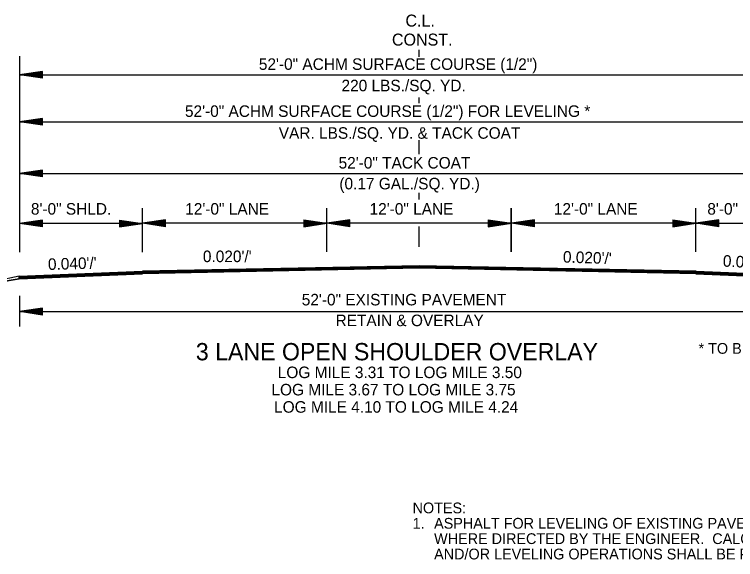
# Model space of a CAD drawing. Extents: x 542112 to 1930787, y -1968972 to 596640.
# Drawn here: x 546718.3 to 547187.5, y -1946518.3 to -1946163.6 of the extents above; entities that cross this region are included whole.
import ezdxf

# ---------------------------------------------------------------- set-up
doc = ezdxf.new("R2010")
doc.units = 0
for name, color, linetype in [('R_Border Notes', 7, 'Continuous'), ('R_Border Prem', 7, 'Continuous'), ('R_Draft', 7, 'Continuous')]:
    doc.layers.add(name, color=color, linetype=linetype)

msp = doc.modelspace()

# ---------------------------------------------------------------- linework, layer by layer
at = {"layer": 'R_Draft'}
for p, q in [((546721.58, -1946190.89), (546721.58, -1946318.31)), ((546981.62, -1946191.17), (546981.62, -1946186.75)), ((546736.66, -1946200.68), (546721.66, -1946202.93)), ((546736.66, -1946205.18), (546736.66, -1946200.68)), ((546721.66, -1946202.93), (547241.62, -1946202.93)), ((546736.66, -1946205.18), (546721.66, -1946202.93)), ((546736.66, -1946201.05), (546724.17, -1946202.93)), ((546736.66, -1946204.8), (546724.17, -1946202.93)), ((546736.66, -1946201.44), (546726.75, -1946202.93)), ((546736.66, -1946204.42), (546726.75, -1946202.93)), ((546736.66, -1946201.81), (546729.25, -1946202.93)), ((546736.66, -1946204.05), (546729.25, -1946202.93)), ((546736.66, -1946202.19), (546731.79, -1946202.93)), ((546736.66, -1946203.66), (546731.79, -1946202.93)), ((546736.66, -1946202.58), (546734.29, -1946202.93)), ((546736.66, -1946203.28), (546734.29, -1946202.93)), ((546981.62, -1946221.3), (546981.62, -1946217.62)), ((546736.62, -1946231.28), (546721.62, -1946233.53)), ((546721.62, -1946233.53), (547241.62, -1946233.53)), ((546736.62, -1946235.78), (546721.62, -1946233.53)), ((546736.62, -1946231.65), (546724.12, -1946233.53)), ((546736.62, -1946235.4), (546724.12, -1946233.53)), ((546736.62, -1946232.03), (546726.7, -1946233.53)), ((546736.62, -1946235.02), (546726.7, -1946233.53)), ((546736.62, -1946232.41), (546729.2, -1946233.53)), ((546736.62, -1946234.64), (546729.2, -1946233.53)), ((546736.62, -1946232.79), (546731.74, -1946233.53)), ((546736.62, -1946234.25), (546731.74, -1946233.53)), ((546736.62, -1946233.17), (546734.25, -1946233.53)), ((546736.62, -1946233.88), (546734.25, -1946233.53)), ((546736.62, -1946235.78), (546736.62, -1946231.28)), ((546981.62, -1946254.65), (546981.62, -1946245.35)), ((546736.62, -1946264.87), (546721.62, -1946267.12)), ((546736.62, -1946265.25), (546724.12, -1946267.12)), ((546736.62, -1946265.63), (546726.7, -1946267.12)), ((546736.62, -1946266.01), (546729.2, -1946267.12)), ((546736.62, -1946266.39), (546731.74, -1946267.12)), ((546736.62, -1946269.37), (546736.62, -1946264.87)), ((546721.62, -1946267.12), (547241.62, -1946267.12)), ((546736.62, -1946269.37), (546721.62, -1946267.12)), ((546736.62, -1946269), (546724.12, -1946267.12)), ((546736.62, -1946268.62), (546726.7, -1946267.12)), ((546736.62, -1946268.24), (546729.2, -1946267.12)), ((546736.62, -1946267.85), (546731.74, -1946267.12)), ((546736.62, -1946266.77), (546734.25, -1946267.12)), ((546736.62, -1946267.48), (546734.25, -1946267.12)), ((546981.62, -1946284.09), (546981.62, -1946279.72)), ((546801.62, -1946318.14), (546801.62, -1946289.59)), ((546801.62, -1946318.31), (546801.62, -1946289.59)), ((546921.62, -1946318.14), (546921.62, -1946289.59)), ((547041.54, -1946299.48), (547041.54, -1946289.59)), ((547041.62, -1946318.14), (547041.62, -1946289.59)), ((547161.62, -1946318.14), (547161.62, -1946289.59)), ((546736.62, -1946297.4), (546721.62, -1946299.65)), ((546736.62, -1946297.78), (546724.12, -1946299.65)), ((546736.62, -1946298.16), (546726.7, -1946299.65)), ((546736.62, -1946298.54), (546729.2, -1946299.65)), ((546736.62, -1946298.92), (546731.74, -1946299.65)), ((546736.62, -1946301.9), (546736.62, -1946297.4)), ((546786.62, -1946297.4), (546801.62, -1946299.65)), ((546786.62, -1946297.4), (546786.62, -1946301.9)), ((546786.62, -1946297.78), (546799.11, -1946299.65)), ((546786.62, -1946298.16), (546796.53, -1946299.65)), ((546786.62, -1946298.54), (546794.03, -1946299.65)), ((546786.62, -1946298.93), (546791.49, -1946299.65)), ((546816.62, -1946297.23), (546801.62, -1946299.48)), ((546816.62, -1946297.61), (546804.12, -1946299.48)), ((546816.62, -1946297.99), (546806.7, -1946299.48)), ((546816.62, -1946298.37), (546809.2, -1946299.48)), ((546816.62, -1946298.75), (546811.74, -1946299.48)), ((546816.62, -1946299.13), (546814.25, -1946299.48)), ((546816.62, -1946301.73), (546816.62, -1946297.23)), ((546906.62, -1946297.23), (546921.62, -1946299.48)), ((546906.62, -1946297.23), (546906.62, -1946301.73)), ((546906.62, -1946297.61), (546919.11, -1946299.48)), ((546906.62, -1946297.99), (546916.53, -1946299.48)), ((546906.62, -1946298.37), (546914.03, -1946299.48)), ((546906.62, -1946298.76), (546911.49, -1946299.48)), ((546906.62, -1946299.13), (546908.99, -1946299.48)), ((546936.62, -1946297.23), (546921.62, -1946299.48)), ((546936.62, -1946297.61), (546924.12, -1946299.48)), ((546936.62, -1946297.99), (546926.7, -1946299.48)), ((546936.62, -1946298.37), (546929.2, -1946299.48)), ((546936.62, -1946298.75), (546931.74, -1946299.48)), ((546936.62, -1946299.13), (546934.25, -1946299.48)), ((546936.62, -1946301.73), (546936.62, -1946297.23)), ((547026.62, -1946297.23), (547041.62, -1946299.48)), ((547026.62, -1946297.23), (547026.62, -1946301.73)), ((547026.62, -1946297.61), (547039.11, -1946299.48)), ((547026.62, -1946297.99), (547036.53, -1946299.48)), ((547026.62, -1946298.37), (547034.03, -1946299.48)), ((547026.62, -1946298.76), (547031.49, -1946299.48)), ((547026.62, -1946299.13), (547028.99, -1946299.48)), ((547056.62, -1946297.23), (547041.62, -1946299.48)), ((547056.62, -1946297.61), (547044.12, -1946299.48)), ((547056.62, -1946297.99), (547046.7, -1946299.48)), ((547056.62, -1946298.37), (547049.2, -1946299.48)), ((547056.62, -1946298.75), (547051.74, -1946299.48)), ((547056.62, -1946299.13), (547054.25, -1946299.48)), ((547056.62, -1946301.73), (547056.62, -1946297.23)), ((547146.62, -1946297.23), (547161.62, -1946299.48)), ((547146.62, -1946297.23), (547146.62, -1946301.73)), ((547146.62, -1946297.61), (547159.11, -1946299.48)), ((547146.62, -1946297.99), (547156.53, -1946299.48)), ((547146.62, -1946298.37), (547154.03, -1946299.48)), ((547146.62, -1946298.76), (547151.49, -1946299.48)), ((547146.62, -1946299.13), (547148.99, -1946299.48)), ((547176.62, -1946297.23), (547161.62, -1946299.48)), ((547176.62, -1946297.61), (547164.12, -1946299.48)), ((547176.62, -1946297.99), (547166.7, -1946299.48)), ((547176.62, -1946298.37), (547169.2, -1946299.48)), ((547176.62, -1946298.75), (547171.74, -1946299.48)), ((547176.62, -1946299.13), (547174.25, -1946299.48)), ((547176.62, -1946301.73), (547176.62, -1946297.23)), ((546801.62, -1946299.65), (546721.62, -1946299.65)), ((546736.62, -1946301.9), (546721.62, -1946299.65)), ((546736.62, -1946301.53), (546724.12, -1946299.65)), ((546736.62, -1946301.15), (546726.7, -1946299.65)), ((546736.62, -1946300.77), (546729.2, -1946299.65)), ((546736.62, -1946300.38), (546731.74, -1946299.65)), ((546736.62, -1946299.3), (546734.25, -1946299.65)), ((546736.62, -1946300.01), (546734.25, -1946299.65)), ((546786.62, -1946299.3), (546788.99, -1946299.65)), ((546786.62, -1946301.9), (546801.62, -1946299.65)), ((546786.62, -1946300.39), (546791.49, -1946299.65)), ((546786.62, -1946301.15), (546796.53, -1946299.65)), ((546786.62, -1946301.53), (546799.11, -1946299.65)), ((546786.62, -1946300.77), (546794.03, -1946299.65)), ((546786.62, -1946300.01), (546788.99, -1946299.65)), ((546921.62, -1946299.48), (546801.62, -1946299.48)), ((546816.62, -1946301.73), (546801.62, -1946299.48)), ((546816.62, -1946301.36), (546804.12, -1946299.48)), ((546816.62, -1946300.98), (546806.7, -1946299.48)), ((546816.62, -1946300.6), (546809.2, -1946299.48)), ((546816.62, -1946300.21), (546811.74, -1946299.48)), ((546816.62, -1946299.84), (546814.25, -1946299.48)), ((546906.62, -1946301.73), (546921.62, -1946299.48)), ((546906.62, -1946300.22), (546911.49, -1946299.48)), ((546906.62, -1946300.98), (546916.53, -1946299.48)), ((546906.62, -1946301.36), (546919.11, -1946299.48)), ((546906.62, -1946300.6), (546914.03, -1946299.48)), ((546906.62, -1946299.84), (546908.99, -1946299.48)), ((547041.62, -1946299.48), (546921.62, -1946299.48)), ((546936.62, -1946301.73), (546921.62, -1946299.48)), ((546936.62, -1946301.36), (546924.12, -1946299.48)), ((546936.62, -1946300.98), (546926.7, -1946299.48)), ((546936.62, -1946300.6), (546929.2, -1946299.48)), ((546936.62, -1946300.21), (546931.74, -1946299.48)), ((546936.62, -1946299.84), (546934.25, -1946299.48)), ((546981.62, -1946314.89), (546981.62, -1946301.6)), ((547026.62, -1946301.73), (547041.62, -1946299.48)), ((547026.62, -1946300.22), (547031.49, -1946299.48)), ((547026.62, -1946300.98), (547036.53, -1946299.48)), ((547026.62, -1946301.36), (547039.11, -1946299.48)), ((547026.62, -1946300.6), (547034.03, -1946299.48)), ((547026.62, -1946299.84), (547028.99, -1946299.48)), ((547041.54, -1946318.14), (547041.54, -1946299.48)), ((547161.62, -1946299.48), (547041.62, -1946299.48)), ((547056.62, -1946301.73), (547041.62, -1946299.48)), ((547056.62, -1946301.36), (547044.12, -1946299.48)), ((547056.62, -1946300.98), (547046.7, -1946299.48)), ((547056.62, -1946300.6), (547049.2, -1946299.48)), ((547056.62, -1946300.21), (547051.74, -1946299.48)), ((547056.62, -1946299.84), (547054.25, -1946299.48)), ((547146.62, -1946301.73), (547161.62, -1946299.48)), ((547146.62, -1946300.22), (547151.49, -1946299.48)), ((547146.62, -1946300.98), (547156.53, -1946299.48)), ((547146.62, -1946301.36), (547159.11, -1946299.48)), ((547146.62, -1946300.6), (547154.03, -1946299.48)), ((547146.62, -1946299.84), (547148.99, -1946299.48)), ((547161.62, -1946299.48), (547241.62, -1946299.48)), ((547176.62, -1946301.73), (547161.62, -1946299.48)), ((547176.62, -1946301.36), (547164.12, -1946299.48)), ((547176.62, -1946300.98), (547166.7, -1946299.48)), ((547176.62, -1946300.6), (547169.2, -1946299.48)), ((547176.62, -1946300.21), (547171.74, -1946299.48)), ((547176.62, -1946299.84), (547174.25, -1946299.48)), ((546981.62, -1946327.09), (546801.62, -1946330.69)), ((546981.62, -1946327.39), (546801.62, -1946330.99)), ((547161.8, -1946330.99), (546981.61, -1946327.39)), ((547161.8, -1946330.69), (546981.62, -1946327.09)), ((546721.36, -1946333.9), (546801.62, -1946330.69)), ((546721.36, -1946334.2), (546801.63, -1946330.99)), ((546721.36, -1946334.5), (546801.64, -1946331.29)), ((546721.36, -1946334.8), (546801.65, -1946331.59)), ((546721.36, -1946335.1), (546801.66, -1946331.89)), ((546981.63, -1946327.69), (546801.63, -1946331.29)), ((546981.63, -1946327.99), (546801.63, -1946331.59)), ((546981.64, -1946328.29), (546801.64, -1946331.89)), ((546981.65, -1946328.59), (546801.65, -1946332.19)), ((546981.65, -1946328.79), (546801.65, -1946332.39)), ((547161.77, -1946332.39), (546981.58, -1946328.79)), ((547161.78, -1946331.89), (546981.59, -1946328.29)), ((547161.77, -1946332.19), (546981.59, -1946328.59)), ((547161.79, -1946331.29), (546981.6, -1946327.69)), ((547161.79, -1946331.59), (546981.6, -1946327.99)), ((547161.76, -1946331.89), (547242.07, -1946335.11)), ((547161.77, -1946331.59), (547242.07, -1946334.8)), ((547161.78, -1946331.29), (547242.07, -1946334.5)), ((547161.79, -1946330.99), (547242.07, -1946334.2)), ((547161.8, -1946330.69), (547242.07, -1946333.9)), ((546721.36, -1946335.6), (546621.29, -1946352.28)), ((546721.36, -1946333.9), (546683.86, -1946341.84)), ((546683.86, -1946341.84), (546721.36, -1946335.6)), ((546721.36, -1946335.4), (546801.68, -1946332.19)), ((546721.36, -1946335.6), (546801.68, -1946332.39)), ((546721.36, -1946335.6), (546721.36, -1946333.9)), ((546721.36, -1946333.9), (546721.36, -1946335.6)), ((546721.36, -1946335.6), (546721.36, -1946335.6)), ((547161.74, -1946332.19), (547242.07, -1946335.41)), ((547161.74, -1946332.39), (547242.08, -1946335.61)), ((546721.62, -1946346.7), (546721.62, -1946366.7)), ((546736.62, -1946354.7), (546721.62, -1946356.95)), ((546736.62, -1946355.07), (546724.12, -1946356.95)), ((546736.62, -1946355.46), (546726.7, -1946356.95)), ((546736.62, -1946359.2), (546736.62, -1946354.7)), ((546721.62, -1946356.95), (547241.62, -1946356.95)), ((546736.62, -1946359.2), (546721.62, -1946356.95)), ((546736.62, -1946358.82), (546724.12, -1946356.95)), ((546736.62, -1946358.44), (546726.7, -1946356.95)), ((546736.62, -1946355.83), (546729.2, -1946356.95)), ((546736.62, -1946358.07), (546729.2, -1946356.95)), ((546736.62, -1946356.21), (546731.74, -1946356.95)), ((546736.62, -1946357.68), (546731.74, -1946356.95)), ((546736.62, -1946356.6), (546734.25, -1946356.95)), ((546736.62, -1946357.3), (546734.25, -1946356.95))]:
    msp.add_line(p, q, dxfattribs=at)

# ---------------------------------------------------------------- texts
at = {"layer": 'R_Border Notes'}
for s, p in [('NOTES: ', (546977.36, -1946488.18)), ('1.', (546977.36, -1946498.18)), ('ASPHALT FOR LEVELING OF EXISTING PAVEMENT SHALL BE PLACED ONLY IF AND', (546991.36, -1946498.18)), ('WHERE DIRECTED BY THE ENGINEER.  CALCULATIONS FOR THE AMOUNT OF LEVELING', (546991.36, -1946508.18)), ('AND/OR LEVELING OPERATIONS SHALL BE PERFORMED BEFORE CONSTRUCTING NOTCH', (546991.36, -1946518.18))]:
    msp.add_text(s, height=7, dxfattribs=at).set_placement(p)
at = {"layer": 'R_Border Prem'}
msp.add_text('* TO BE USED IF AND WHERE DIRECTED BY THE ENGINEER.', height=7, dxfattribs=at).set_placement((547163.42, -1946384.41))
at = {"layer": 'R_Draft'}
for s, height, p in [('C.L.', 7.8, (546972.72, -1946171.55)), ('CONST.', 7.8, (546963.94, -1946183.92)), ('52\'-0" ACHM SURFACE COURSE (1/2")', 7.5, (546877.33, -1946199.71)), ('220 LBS./SQ. YD. ', 7.5, (546931.12, -1946213.65)), ('52\'-0" ACHM SURFACE COURSE (1/2") FOR LEVELING *', 7.5, (546829.26, -1946230.3)), ('VAR. LBS./SQ. YD. & TACK COAT', 7.5, (546890.3, -1946244.52)), ('52\'-0" TACK COAT', 7.5, (546929.22, -1946263.9)), ('(0.17 GAL./SQ. YD.)', 7.5, (546929.72, -1946277.45)), ('8\'-0" SHLD.', 7.5, (546729.01, -1946293.88)), ('12\'-0" LANE', 7.5, (546829.43, -1946293.88)), ('12\'-0" LANE', 7.5, (546949.39, -1946293.88)), ('12\'-0" LANE', 7.5, (547069.3, -1946293.88)), ('8\'-0" SHLD.', 7.5, (547169.14, -1946293.88)), ("0.020'/'", 7.5, (546840.92, -1946324.77)), ('52\'-0" EXISTING PAVEMENT', 7.5, (546905.25, -1946352.93)), ('RETAIN & OVERLAY', 7.5, (546927.25, -1946366.44)), ('3 LANE OPEN SHOULDER OVERLAY', 11.25, (546836.34, -1946388.66)), ('LOG MILE 3.31 TO LOG MILE 3.50', 7.5, (546889.64, -1946400.24)), ('LOG MILE 3.67 TO LOG MILE 3.75', 7.5, (546885.53, -1946411.49)), ('LOG MILE 4.10 TO LOG MILE 4.24', 7.5, (546887.25, -1946422.74))]:
    msp.add_text(s, height=height, dxfattribs=at).set_placement(p)
for s, rotation, p in [("0.020'/'", 358.0607, (547075.08, -1946325.01)), ("0.040'/'", 1.7023, (546740.21, -1946329.92)), ("0.040'/'", 356.9335, (547179.08, -1946327.63))]:
    msp.add_text(s, height=7.5, rotation=rotation, dxfattribs=at).set_placement(p)

doc.saveas('drawing.dxf')
